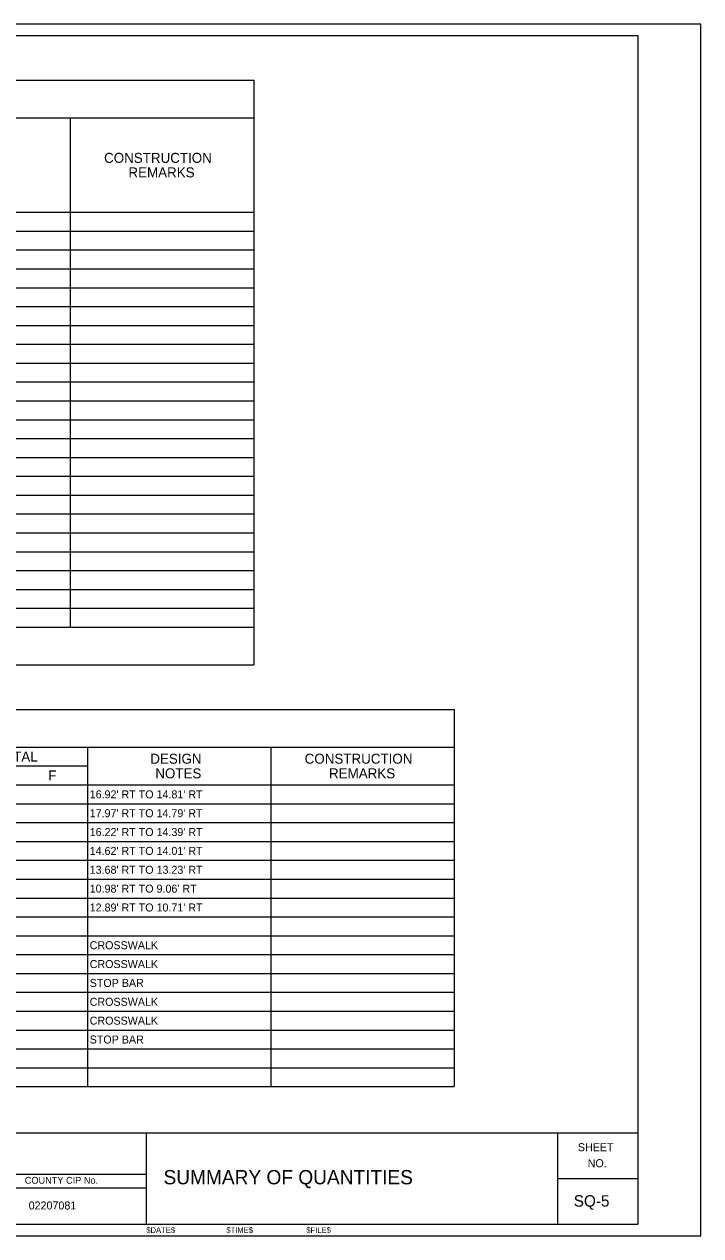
# Model space of a CAD drawing. Extents: x -831.4 to -734.9, y -2212.7 to -2202.1.
# Drawn here: x -740.81 to -734.89, y -2212.74 to -2202.14 of the extents above; entities that cross this region are included whole.
import ezdxf

# ---------------------------------------------------------------- set-up
doc = ezdxf.new("R2010")
doc.units = 0
for name, color, linetype in [('PlotBorder_dp', 7, 'Continuous'), ('SheetBorder_dp', 7, 'Continuous'), ('SheetLines_dp', 7, 'Continuous'), ('SumBoxBorder_dp', 7, 'Continuous'), ('SumBoxLines_dp', 7, 'Continuous'), ('SumBoxLinesMin_dp', 7, 'Continuous'), ('TextLabel', 7, 'Continuous'), ('TextMinor', 7, 'Continuous'), ('TextMisc', 7, 'Continuous'), ('TextShtNo', 7, 'Continuous')]:
    doc.layers.add(name, color=color, linetype=linetype)

msp = doc.modelspace()

# ---------------------------------------------------------------- linework, layer by layer
at = {"layer": 'PlotBorder_dp'}
msp.add_lwpolyline([(-751.391, -2212.74), (-734.891, -2212.74), (-734.891, -2202.14), (-751.391, -2202.14)], close=True, dxfattribs=at)
at = {"layer": 'SheetBorder_dp'}
for p, q in [((-750.841, -2202.24), (-735.441, -2202.24)), ((-735.441, -2202.24), (-735.441, -2212.64)), ((-750.841, -2211.84), (-735.441, -2211.84)), ((-750.841, -2212.64), (-735.441, -2212.64))]:
    msp.add_line(p, q, dxfattribs=at)
at = {"layer": 'SheetLines_dp'}
for p, q in [((-739.741, -2212.64), (-739.741, -2211.84)), ((-736.141, -2212.64), (-736.141, -2211.84)), ((-742.741, -2212.2), (-739.741, -2212.2)), ((-742.741, -2212.32), (-739.741, -2212.32)), ((-736.141, -2212.24), (-735.441, -2212.24))]:
    msp.add_line(p, q, dxfattribs=at)
at = {"layer": 'SumBoxBorder_dp'}
for p, q in [((-747.479, -2202.63), (-738.802, -2202.63)), ((-738.802, -2202.63), (-738.802, -2207.745)), ((-747.479, -2207.745), (-738.802, -2207.745)), ((-749.407, -2208.135), (-737.047, -2208.135)), ((-737.047, -2208.135), (-737.047, -2211.435)), ((-749.407, -2211.435), (-737.047, -2211.435))]:
    msp.add_line(p, q, dxfattribs=at)
at = {"layer": 'SumBoxLines_dp'}
for p, q in [((-747.479, -2202.96), (-738.802, -2202.96)), ((-747.479, -2202.96), (-738.802, -2202.96)), ((-740.407, -2202.96), (-740.407, -2207.415)), ((-740.407, -2202.96), (-740.407, -2207.415)), ((-747.479, -2203.785), (-738.802, -2203.785)), ((-747.479, -2203.785), (-738.802, -2203.785)), ((-742.012, -2207.415), (-738.802, -2207.415)), ((-749.407, -2208.465), (-737.047, -2208.465)), ((-749.407, -2208.465), (-737.047, -2208.465)), ((-740.257, -2208.465), (-740.257, -2211.435)), ((-740.257, -2208.465), (-740.257, -2211.435)), ((-738.652, -2208.465), (-738.652, -2211.435)), ((-738.652, -2208.465), (-738.652, -2211.435)), ((-742.687, -2208.63), (-740.257, -2208.63)), ((-749.407, -2208.795), (-737.047, -2208.795))]:
    msp.add_line(p, q, dxfattribs=at)
at = {"layer": 'SumBoxLinesMin_dp'}
for p, q in [((-747.479, -2203.95), (-738.802, -2203.95)), ((-747.479, -2203.95), (-738.802, -2203.95)), ((-747.479, -2204.115), (-738.802, -2204.115)), ((-747.479, -2204.115), (-738.802, -2204.115)), ((-747.479, -2204.28), (-738.802, -2204.28)), ((-747.479, -2204.28), (-738.802, -2204.28)), ((-747.479, -2204.445), (-738.802, -2204.445)), ((-747.479, -2204.445), (-738.802, -2204.445)), ((-747.479, -2204.61), (-738.802, -2204.61)), ((-747.479, -2204.61), (-738.802, -2204.61)), ((-747.479, -2204.775), (-738.802, -2204.775)), ((-747.479, -2204.775), (-738.802, -2204.775)), ((-747.479, -2204.94), (-738.802, -2204.94)), ((-747.479, -2204.94), (-738.802, -2204.94)), ((-747.479, -2205.105), (-738.802, -2205.105)), ((-747.479, -2205.105), (-738.802, -2205.105)), ((-747.479, -2205.27), (-738.802, -2205.27)), ((-747.479, -2205.27), (-738.802, -2205.27)), ((-747.479, -2205.435), (-738.802, -2205.435)), ((-747.479, -2205.435), (-738.802, -2205.435)), ((-747.479, -2205.6), (-738.802, -2205.6)), ((-747.479, -2205.6), (-738.802, -2205.6)), ((-747.479, -2205.765), (-738.802, -2205.765)), ((-747.479, -2205.765), (-738.802, -2205.765)), ((-747.479, -2205.93), (-738.802, -2205.93)), ((-747.479, -2205.93), (-738.802, -2205.93)), ((-747.479, -2206.095), (-738.802, -2206.095)), ((-747.479, -2206.095), (-738.802, -2206.095)), ((-747.479, -2206.26), (-738.802, -2206.26)), ((-747.479, -2206.26), (-738.802, -2206.26)), ((-747.479, -2206.425), (-738.802, -2206.425)), ((-747.479, -2206.425), (-738.802, -2206.425)), ((-747.479, -2206.59), (-738.802, -2206.59)), ((-747.479, -2206.59), (-738.802, -2206.59)), ((-747.479, -2206.755), (-738.802, -2206.755)), ((-747.479, -2206.755), (-738.802, -2206.755)), ((-747.479, -2206.92), (-738.802, -2206.92)), ((-747.479, -2206.92), (-738.802, -2206.92)), ((-747.479, -2207.085), (-738.802, -2207.085)), ((-747.479, -2207.085), (-738.802, -2207.085)), ((-747.479, -2207.25), (-738.802, -2207.25)), ((-747.479, -2207.25), (-738.802, -2207.25)), ((-749.407, -2208.96), (-737.047, -2208.96)), ((-749.407, -2208.96), (-737.047, -2208.96)), ((-749.407, -2209.125), (-737.047, -2209.125)), ((-749.407, -2209.125), (-737.047, -2209.125)), ((-749.407, -2209.29), (-737.047, -2209.29)), ((-749.407, -2209.29), (-737.047, -2209.29)), ((-749.407, -2209.455), (-737.047, -2209.455)), ((-749.407, -2209.455), (-737.047, -2209.455)), ((-749.407, -2209.62), (-737.047, -2209.62)), ((-749.407, -2209.62), (-737.047, -2209.62)), ((-749.407, -2209.785), (-737.047, -2209.785)), ((-749.407, -2209.785), (-737.047, -2209.785)), ((-749.407, -2209.95), (-737.047, -2209.95)), ((-749.407, -2209.95), (-737.047, -2209.95)), ((-749.407, -2210.115), (-737.047, -2210.115)), ((-749.407, -2210.115), (-737.047, -2210.115)), ((-749.407, -2210.28), (-737.047, -2210.28)), ((-749.407, -2210.28), (-737.047, -2210.28)), ((-749.407, -2210.445), (-737.047, -2210.445)), ((-749.407, -2210.445), (-737.047, -2210.445)), ((-749.407, -2210.61), (-737.047, -2210.61)), ((-749.407, -2210.61), (-737.047, -2210.61)), ((-749.407, -2210.775), (-737.047, -2210.775)), ((-749.407, -2210.775), (-737.047, -2210.775)), ((-749.407, -2210.94), (-737.047, -2210.94)), ((-749.407, -2210.94), (-737.047, -2210.94)), ((-749.407, -2211.105), (-737.047, -2211.105)), ((-749.407, -2211.105), (-737.047, -2211.105)), ((-749.407, -2211.27), (-737.047, -2211.27)), ((-749.407, -2211.27), (-737.047, -2211.27))]:
    msp.add_line(p, q, dxfattribs=at)

# ---------------------------------------------------------------- texts
at = {"layer": 'TextLabel'}
for s, height, p in [('CONSTRUCTION', 0.0875, (-740.111, -2203.353)), ('REMARKS', 0.0875, (-739.898, -2203.48)), ('TOTAL', 0.0875, (-741.069, -2208.591)), ('DESIGN', 0.0875, (-739.707, -2208.61)), ('CONSTRUCTION', 0.0875, (-738.356, -2208.61)), ('F', 0.0875, (-740.599, -2208.756)), ('NOTES', 0.0875, (-739.663, -2208.738)), ('REMARKS', 0.0875, (-738.143, -2208.738)), ("16.92' RT TO 14.81' RT", 0.07, (-740.237, -2208.913)), ("17.97' RT TO 14.79' RT", 0.07, (-740.237, -2209.078)), ("16.22' RT TO 14.39' RT", 0.07, (-740.237, -2209.243)), ("14.62' RT TO 14.01' RT", 0.07, (-740.237, -2209.408)), ("13.68' RT TO 13.23' RT", 0.07, (-740.237, -2209.573)), ("10.98' RT TO 9.06' RT", 0.07, (-740.237, -2209.738)), ("12.89' RT TO 10.71' RT", 0.07, (-740.237, -2209.903)), ('CROSSWALK', 0.07, (-740.237, -2210.233)), ('CROSSWALK', 0.07, (-740.237, -2210.398)), ('STOP BAR', 0.07, (-740.237, -2210.563)), ('CROSSWALK', 0.07, (-740.237, -2210.728)), ('CROSSWALK', 0.07, (-740.237, -2210.893)), ('STOP BAR', 0.07, (-740.237, -2211.058))]:
    msp.add_text(s, height=height, dxfattribs=at).set_placement(p)
at = {"layer": 'TextMinor'}
for s, p in [('$DATE$', (-739.742, -2212.715)), ('$TIME$', (-739.042, -2212.715)), ('$FILE$', (-738.342, -2212.715))]:
    msp.add_text(s, height=0.05, rotation=360, dxfattribs=at).set_placement(p)
at = {"layer": 'TextMisc'}
for s, height, rotation, p in [('SHEET', 0.07, 359.8607, (-735.966, -2212)), ('NO.', 0.07, 359.8607, (-735.88, -2212.14)), ('COUNTY CIP No.', 0.06, 360, (-740.805, -2212.285)), ('   02207081   ', 0.07, 360, (-740.849, -2212.51))]:
    msp.add_text(s, height=height, rotation=rotation, dxfattribs=at).set_placement(p)
msp.add_text('    SUMMARY OF QUANTITIES      ', height=0.125, dxfattribs=at).set_placement((-739.777, -2212.29))
at = {"layer": 'TextShtNo'}
msp.add_text(' SQ-5 ', height=0.1, dxfattribs=at).set_placement((-736.039, -2212.485))

doc.saveas('drawing.dxf')
